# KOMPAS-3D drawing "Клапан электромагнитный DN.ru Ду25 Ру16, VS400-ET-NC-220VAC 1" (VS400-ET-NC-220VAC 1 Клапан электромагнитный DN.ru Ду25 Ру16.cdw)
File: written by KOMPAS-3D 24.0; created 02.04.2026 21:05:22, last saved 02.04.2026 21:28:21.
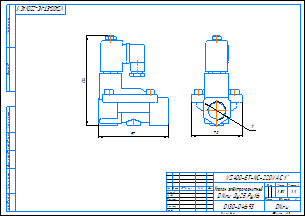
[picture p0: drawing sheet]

Document properties: c3d_UniqueCompID: ef56311e-7521-43dc-8291-0e6108b3d81d; Обозначение: VS400-ET-NC-220VAC 1; Наименование: Клапан электромагнитный DN.ru Ду25 Ру16; Автор: artio; Класс точности: c; Знак неуказанной шероховатости: Шероховатость не задана; Рассекать на разрезах: Да; c3d_UniqueCompID: ef56311e-7521-43dc-8291-0e6108b3d81d; Обозначение: VS400-ET-NC-220VAC 1-2; Наименование: Клапан электромагнитный DN.ru Ду15 Ру16; Автор: artio; Класс точности: c; Знак неуказанной шероховатости: Шероховатость не задана; Рассекать на разрезах: Да; c3d_UniqueCompID: ef56311e-7521-43dc-8291-0e6108b3d81d; Обозначение: VS400-ET-NC-220VAC 3-4; Наименование: Клапан электромагнитный DN.ru Ду20 Ру16; Автор: artio; Класс точности: c; Знак неуказанной шероховатости: Шероховатость не задана; Рассекать на разрезах: Да; c3d_UniqueCompID: ef56311e-7521-43dc-8291-0e6108b3d81d; Обозначение: VS400-ET-NC-220VAC 3-8; Наименование: Клапан электромагнитный DN.ru Ду10 Ру16; Автор: artio; Класс точности: c; Знак неуказанной шероховатости: Шероховатость не задана; Рассекать на разрезах: Да; Автор: artio; Форматы листов документа: A3; Полное имя файла: VS400-ET-NC-220VAC 1 Клапан электромагнитный DN.ru Ду25 Ру16.m3d; Масса: 1.524; Наименование: Клапан электромагнитный DN.ru Ду25 Ру16; Количество листов документа: 1; Примечание: D130-04693

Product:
- Body: Тело 1  | qty 1
    Масса: 1.76797
- Part/product: Клапан электромагнитный DN.ru Ду25 Ру16  | designation VS400-ET-NC-220VAC 1
    Масса: 1.524
    Раздел спецификации: Прочие изделия
    Примечание: D130-04693
    additional columns: ef56311e-7521-43dc-8291-0e6108b3d81d; VS400-ET-NC-220VAC 1; artio; c; Шероховатость не задана; Да

Views: Вид 1, Спереди, Проекционный вид 2
Referenced files in C:\Users\artio\OneDrive\Рабочий стол\Клапан электромагнитный DN.ru VS4x-xT-NC-x\DN10\: VS400-ET-NC-220VAC 3-8 Клапан электромагнитный DN.ru Ду10 Ру16.m3d, VS400-ET-NC-220VAC 3-8 Клапан электромагнитный DN.ru Ду10 Ру16.cdw
Referenced files in C:\Users\artio\OneDrive\Рабочий стол\Клапан электромагнитный DN.ru VS4x-xT-NC-x\DN25\: VS400-ET-NC-220VAC 1 Клапан электромагнитный DN.ru Ду25 Ру16.m3d
Referenced files in C:\Users\artio\OneDrive\Рабочий стол\Клапан электромагнитный DN.ru\VS400\VS400-ET-NC\VS400-ET-NC-220VAC\Ду25\: VS400-ET-NC-220VAC 1 Клапан электромагнитный DN.ru Ду25 Ру16.m3d
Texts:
  VS400-ET-NC-220VAC 1
  Линейный размер
  Клапан электромагнитный
  DN.ru Ду25 Ру16
  VS400-ET-NC-220VAC 1"
  VS400-ET-NC-220VAC 1"-
  Клапан электромагнитный DN.ru Ду25 Ру16
  VS400-ET-NC-220VAC 1 Клапан электромагнитный DN.ru Ду25 Ру16
Dimensions and other numbers on the sheet: 0; 3; 2; 4; 70; 97; 124; 1:1; 1; 1,52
